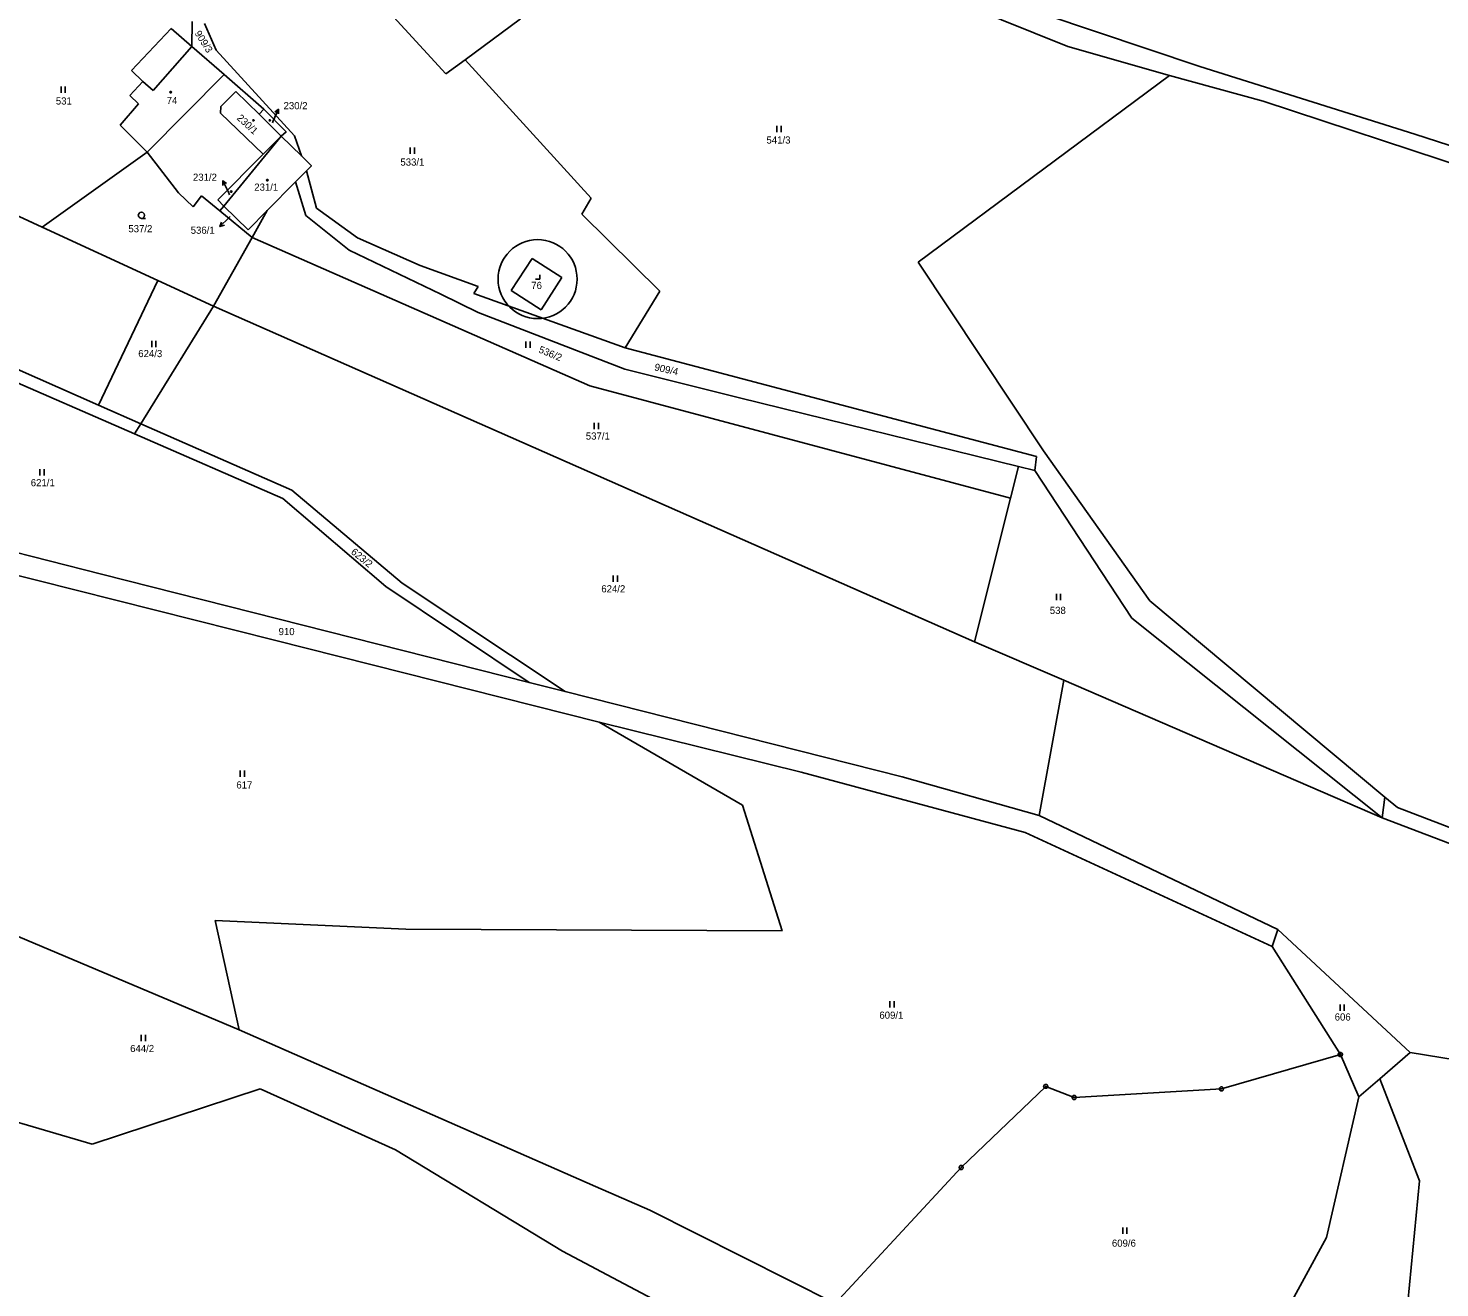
# Model space of a CAD drawing. Extents: x -580551 to -575069, y -1073031 to -1067931.
# Drawn here: x -578084.3 to -577749.4, y -1070721.5 to -1070422.6 of the extents above; entities that cross this region are included whole.
import ezdxf

# ---------------------------------------------------------------- set-up
doc = ezdxf.new("R2010")
doc.units = 0
for name, color, linetype in [('Druh pozemku', 7, 'Continuous'), ('Geodetické body', 7, 'Continuous'), ('Parcela', 7, 'Continuous'), ('Parcelní číslo', 7, 'Continuous'), ('Parcelní číslo_stavba', 7, 'Continuous'), ('Pomocná vrstva', 7, 'Continuous'), ('SR - hranice státu', 7, 'Continuous'), ('stavební parcely', 7, 'Continuous'), ('Vnitřní kresba', 7, 'Continuous'), ('Vrstva 6', 7, 'Continuous')]:
    doc.layers.add(name, color=color, linetype=linetype)

msp = doc.modelspace()

# ---------------------------------------------------------------- linework, layer by layer
at = {"layer": 'Druh pozemku'}
for p, q in [((-578076.49, -1070436.43), (-578076.49, -1070437.93)), ((-578075.49, -1070437.93), (-578075.49, -1070436.43)), ((-577906.63, -1070445.75), (-577906.63, -1070447.25)), ((-577905.63, -1070447.25), (-577905.63, -1070445.75)), ((-577993.62, -1070450.85), (-577993.62, -1070452.35)), ((-577992.62, -1070452.35), (-577992.62, -1070450.85)), ((-578054.97, -1070496.75), (-578054.97, -1070498.25)), ((-578053.97, -1070498.25), (-578053.97, -1070496.75)), ((-577966.19, -1070496.89), (-577966.19, -1070498.39)), ((-577965.19, -1070498.39), (-577965.19, -1070496.89)), ((-577949.96, -1070516.2), (-577949.96, -1070517.7)), ((-577948.96, -1070517.7), (-577948.96, -1070516.2)), ((-578081.49, -1070527.19), (-578081.49, -1070528.69)), ((-578080.49, -1070528.69), (-578080.49, -1070527.19)), ((-577945.49, -1070552.45), (-577945.49, -1070553.95)), ((-577944.49, -1070553.95), (-577944.49, -1070552.45)), ((-577840.32, -1070556.76), (-577840.32, -1070558.26)), ((-577839.32, -1070558.26), (-577839.32, -1070556.76)), ((-578033.98, -1070598.73), (-578033.98, -1070600.23)), ((-578032.98, -1070600.23), (-578032.98, -1070598.73)), ((-577879.8, -1070653.48), (-577879.8, -1070654.98)), ((-577878.8, -1070654.98), (-577878.8, -1070653.48)), ((-577773.02, -1070654.22), (-577773.02, -1070655.72)), ((-577772.02, -1070655.72), (-577772.02, -1070654.22)), ((-578057.48, -1070661.46), (-578057.48, -1070662.96)), ((-578056.48, -1070662.96), (-578056.48, -1070661.46)), ((-577824.57, -1070707.17), (-577824.57, -1070708.67)), ((-577823.57, -1070708.67), (-577823.57, -1070707.17))]:
    msp.add_line(p, q, dxfattribs=at)
for points in [[(-578050.38, -1070437.59), (-578050.29, -1070437.74), (-578050.38, -1070437.89), (-578050.56, -1070437.89), (-578050.65, -1070437.74), (-578050.56, -1070437.59)], [(-578030.75, -1070444.28), (-578030.66, -1070444.43), (-578030.75, -1070444.58), (-578030.93, -1070444.58), (-578031.02, -1070444.43), (-578030.93, -1070444.28)], [(-578026.85, -1070444.28), (-578026.76, -1070444.43), (-578026.85, -1070444.58), (-578027.03, -1070444.58), (-578027.12, -1070444.43), (-578027.03, -1070444.28)], [(-578027.45, -1070458.48), (-578027.36, -1070458.63), (-578027.45, -1070458.78), (-578027.63, -1070458.78), (-578027.72, -1070458.63), (-578027.63, -1070458.48)], [(-578036.02, -1070461.19), (-578035.93, -1070461.34), (-578036.02, -1070461.49), (-578036.2, -1070461.49), (-578036.29, -1070461.34), (-578036.2, -1070461.19)]]:
    msp.add_lwpolyline(points, close=True, dxfattribs=at)
for points in [[(-578057.41, -1070467.69), (-578057.79, -1070467.59), (-578058.06, -1070467.32), (-578058.16, -1070466.95), (-578058.06, -1070466.58), (-578057.79, -1070466.31), (-578057.42, -1070466.21), (-578057.05, -1070466.31), (-578056.78, -1070466.58), (-578056.68, -1070466.96), (-578056.78, -1070467.34), (-578057.05, -1070467.61), (-578057.43, -1070467.71), (-578056.43, -1070467.71)], [(-577963.91, -1070482.11), (-577962.91, -1070482.11), (-577962.91, -1070481.11)]]:
    msp.add_lwpolyline(points, dxfattribs=at)
at = {"layer": 'Geodetické body'}
for p, q in [((-577773.06, -1070666.13), (-577772.82, -1070666.13)), ((-577842.96, -1070673.67), (-577842.72, -1070673.67)), ((-577836.22, -1070676.32), (-577835.98, -1070676.32)), ((-577801.28, -1070674.28), (-577801.04, -1070674.28)), ((-577863.02, -1070692.92), (-577862.78, -1070692.92))]:
    msp.add_line(p, q, dxfattribs=at)
for points in [[(-577772.79, -1070665.65), (-577772.54, -1070665.83), (-577772.44, -1070666.12), (-577772.54, -1070666.41), (-577772.79, -1070666.59), (-577773.1, -1070666.59), (-577773.35, -1070666.41), (-577773.45, -1070666.12), (-577773.35, -1070665.83), (-577773.1, -1070665.65)], [(-577842.69, -1070673.19), (-577842.44, -1070673.37), (-577842.34, -1070673.66), (-577842.44, -1070673.95), (-577842.69, -1070674.13), (-577843, -1070674.13), (-577843.25, -1070673.95), (-577843.35, -1070673.66), (-577843.25, -1070673.37), (-577843, -1070673.19)], [(-577801.01, -1070673.8), (-577800.76, -1070673.98), (-577800.66, -1070674.27), (-577800.76, -1070674.56), (-577801.01, -1070674.74), (-577801.32, -1070674.74), (-577801.57, -1070674.56), (-577801.67, -1070674.27), (-577801.57, -1070673.98), (-577801.32, -1070673.8)], [(-577835.95, -1070675.84), (-577835.7, -1070676.02), (-577835.6, -1070676.31), (-577835.7, -1070676.6), (-577835.95, -1070676.78), (-577836.26, -1070676.78), (-577836.51, -1070676.6), (-577836.61, -1070676.31), (-577836.51, -1070676.02), (-577836.26, -1070675.84)], [(-577862.75, -1070692.44), (-577862.5, -1070692.62), (-577862.4, -1070692.91), (-577862.5, -1070693.2), (-577862.75, -1070693.38), (-577863.06, -1070693.38), (-577863.31, -1070693.2), (-577863.41, -1070692.91), (-577863.31, -1070692.62), (-577863.06, -1070692.44)]]:
    msp.add_lwpolyline(points, close=True, dxfattribs=at)
at = {"layer": 'Parcela'}
for p, q in [((-577858.45, -1070414.11), (-577806.32, -1070431.64)), ((-577985.2, -1070433.39), (-578000.19, -1070417.03)), ((-577861.42, -1070417.31), (-577837.64, -1070426.87)), ((-578050.36, -1070422.66), (-578059.76, -1070432.64)), ((-578045.43, -1070426.94), (-578050.36, -1070422.66)), ((-578045.35, -1070420.96), (-578045.43, -1070426.94)), ((-578039.68, -1070427.74), (-578042.48, -1070421.46)), ((-577980.64, -1070430.04), (-577967.46, -1070420.37)), ((-578037.79, -1070433.58), (-578045.43, -1070426.94)), ((-578021.11, -1070448.13), (-578039.68, -1070427.74)), ((-577837.64, -1070426.87), (-577813.45, -1070433.76)), ((-578059.76, -1070432.64), (-578057.07, -1070435.25)), ((-577985.2, -1070433.39), (-577980.64, -1070430.04)), ((-577950.73, -1070462.87), (-577980.64, -1070430.04)), ((-577806.32, -1070431.64), (-577755.23, -1070447.68)), ((-578057.07, -1070435.25), (-578060.17, -1070438.55)), ((-578028.34, -1070441.78), (-578037.79, -1070433.58)), ((-577873.09, -1070478.05), (-577813.45, -1070433.76)), ((-577813.45, -1070433.76), (-577791.25, -1070439.87)), ((-578058.08, -1070440.52), (-578060.17, -1070438.55)), ((-578035, -1070437.61), (-578038.57, -1070441.16)), ((-578029.52, -1070442.98), (-578035, -1070437.61)), ((-578062.5, -1070445.61), (-578058.08, -1070440.52)), ((-578038.57, -1070441.16), (-578038.69, -1070442.76)), ((-578038.69, -1070442.76), (-578028.5, -1070452.45)), ((-578028.34, -1070441.78), (-578029.52, -1070442.98)), ((-578029.52, -1070442.98), (-578024.23, -1070448.15)), ((-578023.11, -1070447.18), (-578028.34, -1070441.78)), ((-577791.25, -1070439.87), (-577736.35, -1070458)), ((-578056.05, -1070452.02), (-578062.5, -1070445.61)), ((-578037.85, -1070464.77), (-578024.23, -1070448.15)), ((-578028.5, -1070452.45), (-578024.23, -1070448.15)), ((-578024.23, -1070448.15), (-578023.11, -1070447.18)), ((-578019.47, -1070452.88), (-578024.23, -1070448.15)), ((-578019.47, -1070452.88), (-578021.11, -1070448.13)), ((-577755.23, -1070447.68), (-577706.55, -1070463.5)), ((-578081, -1070469.8), (-578056.05, -1070452.02)), ((-578048.63, -1070461.67), (-578056.05, -1070452.02)), ((-578028.5, -1070452.45), (-578039.3, -1070463.33)), ((-578017.1, -1070455.23), (-578019.47, -1070452.88)), ((-578020.86, -1070459.03), (-578018.26, -1070456.4)), ((-578018.26, -1070456.4), (-578017.1, -1070455.23)), ((-578015.87, -1070465.23), (-578018.26, -1070456.4)), ((-578081, -1070469.8), (-578108.53, -1070457.02)), ((-578027.58, -1070465.83), (-578020.86, -1070459.03)), ((-578018.38, -1070467.02), (-578020.86, -1070459.03)), ((-578045.14, -1070464.94), (-578048.63, -1070461.67)), ((-578043.16, -1070462.33), (-578045.14, -1070464.94)), ((-578038.81, -1070465.92), (-578043.16, -1070462.33)), ((-577952.89, -1070466.69), (-577950.73, -1070462.87)), ((-578039.3, -1070463.33), (-578037.85, -1070464.77)), ((-578037.85, -1070464.77), (-578038.81, -1070465.92)), ((-578031.16, -1070472.23), (-578038.81, -1070465.92)), ((-578037.85, -1070464.77), (-578032.12, -1070470.43)), ((-578032.12, -1070470.43), (-578027.58, -1070465.83)), ((-578031.16, -1070472.23), (-578027.58, -1070465.83)), ((-578006.17, -1070472.31), (-578015.87, -1070465.23)), ((-578053.52, -1070482.42), (-578081, -1070469.8)), ((-578008.12, -1070475.24), (-578018.38, -1070467.02)), ((-577934.42, -1070484.95), (-577952.89, -1070466.69)), ((-578040.28, -1070488.5), (-578031.16, -1070472.23)), ((-578031.16, -1070472.23), (-577951.01, -1070507.41)), ((-577991.26, -1070478.87), (-578006.17, -1070472.31)), ((-577986.41, -1070485.64), (-578008.12, -1070475.24)), ((-577977.51, -1070483.83), (-577991.26, -1070478.87)), ((-577964.73, -1070477.2), (-577969.65, -1070484.81)), ((-577964.73, -1070477.2), (-577957.68, -1070481.75)), ((-577843.37, -1070522.88), (-577873.09, -1070478.05)), ((-578040.28, -1070488.5), (-578053.52, -1070482.42)), ((-577957.68, -1070481.75), (-577962.6, -1070489.37)), ((-577977.48, -1070490.01), (-577986.41, -1070485.64)), ((-577978.51, -1070485.51), (-577977.51, -1070483.83)), ((-577942.6, -1070498.45), (-577978.51, -1070485.51)), ((-577962.6, -1070489.37), (-577969.65, -1070484.81)), ((-577942.6, -1070498.45), (-577934.42, -1070484.95)), ((-578040.28, -1070488.5), (-578057.58, -1070516.47)), ((-577859.74, -1070568.14), (-578040.28, -1070488.5)), ((-578059.03, -1070518.81), (-578118.06, -1070493.1)), ((-578067.62, -1070512.04), (-578117.01, -1070490.23)), ((-577942.71, -1070503.45), (-577977.48, -1070490.01)), ((-577845.02, -1070524.18), (-577942.6, -1070498.45)), ((-577915.51, -1070510.28), (-577942.71, -1070503.45)), ((-577951.01, -1070507.41), (-577851.18, -1070534.1)), ((-578057.58, -1070516.47), (-578067.62, -1070512.04)), ((-577849.28, -1070526.57), (-577915.51, -1070510.28)), ((-578057.58, -1070516.47), (-578059.03, -1070518.81)), ((-578021.77, -1070532.22), (-578057.58, -1070516.47)), ((-578023.85, -1070534.14), (-578059.03, -1070518.81)), ((-577818.13, -1070558.45), (-577843.37, -1070522.88)), ((-578066.89, -1070552.12), (-578168.38, -1070526.44)), ((-577851.18, -1070534.1), (-577849.28, -1070526.57)), ((-577845.44, -1070527.51), (-577849.28, -1070526.57)), ((-577845.44, -1070527.51), (-577845.02, -1070524.18)), ((-577822.38, -1070562.53), (-577845.44, -1070527.51)), ((-577995.56, -1070554.22), (-578021.77, -1070532.22)), ((-577999.43, -1070555.03), (-578023.85, -1070534.14)), ((-577859.74, -1070568.14), (-577851.18, -1070534.1)), ((-578128.28, -1070541.99), (-578025.83, -1070567.81)), ((-577965.4, -1070577.8), (-578066.89, -1070552.12)), ((-577965.4, -1070577.8), (-577999.43, -1070555.03)), ((-577956.88, -1070579.95), (-577995.56, -1070554.22)), ((-577762.39, -1070605.01), (-577818.13, -1070558.45)), ((-577763.03, -1070609.98), (-577822.38, -1070562.53)), ((-578025.83, -1070567.81), (-577948.83, -1070587.22)), ((-577838.56, -1070577.3), (-577859.74, -1070568.14)), ((-577956.88, -1070579.95), (-577965.4, -1070577.8)), ((-577876.88, -1070600.19), (-577956.88, -1070579.95)), ((-577844.43, -1070609.36), (-577838.56, -1070577.3)), ((-577763.03, -1070609.98), (-577838.56, -1070577.3)), ((-577948.83, -1070587.22), (-577900.88, -1070599.08)), ((-577900.88, -1070599.08), (-577847.72, -1070613.45)), ((-577844.43, -1070609.36), (-577876.88, -1070600.19)), ((-577763.03, -1070609.98), (-577762.39, -1070605.01)), ((-577759.37, -1070607.53), (-577762.39, -1070605.01)), ((-577787.8, -1070636.45), (-577844.43, -1070609.36)), ((-577644.65, -1070654.99), (-577763.03, -1070609.98)), ((-577640.62, -1070652.74), (-577759.37, -1070607.53)), ((-577847.72, -1070613.45), (-577789.13, -1070640.45)), ((-578034.23, -1070660.29), (-578144.08, -1070613.9)), ((-577787.8, -1070636.45), (-577789.13, -1070640.45)), ((-577756.39, -1070665.66), (-577787.8, -1070636.45)), ((-577772.94, -1070666.13), (-577789.13, -1070640.45)), ((-577949.7, -1070697.42), (-578034.23, -1070660.29)), ((-577801.16, -1070674.28), (-577772.94, -1070666.13)), ((-577772.94, -1070666.13), (-577768.53, -1070676.17)), ((-577756.39, -1070665.66), (-577763.54, -1070671.85)), ((-577737.46, -1070668.67), (-577756.39, -1070665.66)), ((-577862.9, -1070692.92), (-577842.84, -1070673.67)), ((-577842.84, -1070673.67), (-577836.1, -1070676.32)), ((-577763.54, -1070671.85), (-577768.53, -1070676.17)), ((-577763.54, -1070671.85), (-577754.19, -1070696.06)), ((-578069.14, -1070687.4), (-578103.62, -1070677.27)), ((-578029.21, -1070674.26), (-578069.14, -1070687.4)), ((-577997.17, -1070688.7), (-578029.21, -1070674.26)), ((-577836.1, -1070676.32), (-577801.16, -1070674.28)), ((-577768.53, -1070676.17), (-577776.19, -1070709.56)), ((-577957.53, -1070712.79), (-577997.17, -1070688.7)), ((-577892.84, -1070725.17), (-577862.9, -1070692.92)), ((-577936.81, -1070703.08), (-577949.7, -1070697.42)), ((-577754.19, -1070696.06), (-577761.83, -1070777.01)), ((-577892.84, -1070725.17), (-577936.81, -1070703.08)), ((-577776.19, -1070709.56), (-577804.68, -1070761.47)), ((-577916.6, -1070734.36), (-577957.53, -1070712.79))]:
    msp.add_line(p, q, dxfattribs=at)
at = {"layer": 'Pomocná vrstva'}
for p, q in [((-578024.931, -1070441.8), (-578026.13, -1070444.55)), ((-578026.32, -1070444.99), (-578026.13, -1070444.55)), ((-578038.095, -1070458.769), (-578036.79, -1070461.47)), ((-578036.5, -1070462.08), (-578036.79, -1070461.47)), ((-578038.809, -1070469.654), (-578036.67, -1070467.55)), ((-578036.36, -1070467.24), (-578036.67, -1070467.55))]:
    msp.add_line(p, q, dxfattribs=at)
for points in [[(-578025.789, -1070442.517), (-578024.931, -1070441.8), (-578024.872, -1070442.917)], [(-578038.11, -1070459.887), (-578038.095, -1070458.769), (-578037.21, -1070459.452)], [(-578037.745, -1070469.309), (-578038.809, -1070469.654), (-578038.446, -1070468.596)]]:
    msp.add_lwpolyline(points, dxfattribs=at)
at = {"layer": 'SR - hranice státu'}
for points in [[(-578028.34, -1070441.78), (-578037.79, -1070433.58), (-578045.43, -1070426.94), (-578045.35, -1070420.96)], [(-578040.28, -1070488.5), (-578031.16, -1070472.23), (-578027.58, -1070465.83), (-578020.86, -1070459.03), (-578017.1, -1070455.23), (-578019.47, -1070452.88), (-578024.23, -1070448.15), (-578023.11, -1070447.18), (-578028.34, -1070441.78)], [(-578109.99, -1070456.34), (-578108.53, -1070457.02), (-578081, -1070469.8), (-578053.52, -1070482.42), (-578040.28, -1070488.5)]]:
    msp.add_lwpolyline(points, dxfattribs=at)
at = {"layer": 'stavební parcely'}
msp.add_circle((-577963.41, -1070482.11), 9.375, dxfattribs=at)
at = {"layer": 'Vnitřní kresba'}
for p, q in [((-578054.67, -1070437.33), (-578045.43, -1070426.94)), ((-578057.07, -1070435.25), (-578054.67, -1070437.33)), ((-578056.05, -1070452.02), (-578037.79, -1070433.58))]:
    msp.add_line(p, q, dxfattribs=at)
at = {"layer": 'Vrstva 6'}
for p, q in [((-578067.62, -1070512.04), (-578053.52, -1070482.42)), ((-577914.77, -1070606.9), (-577948.83, -1070587.22)), ((-577905.41, -1070636.76), (-577914.77, -1070606.9)), ((-578034.23, -1070660.29), (-578039.94, -1070634.32)), ((-578039.94, -1070634.32), (-577994.66, -1070636.34)), ((-577994.66, -1070636.34), (-577905.41, -1070636.76))]:
    msp.add_line(p, q, dxfattribs=at)

# ---------------------------------------------------------------- texts
at = {"layer": 'Parcelní číslo'}
for s, rotation, p in [('909/3', 302.57901, (-578044.875, -1070423.793)), ('536/2', 337.52944, (-577963.329, -1070499.452)), ('909/4', 347.61349, (-577935.812, -1070503.745)), ('623/2', 321.08555, (-578007.848, -1070547.117))]:
    msp.add_text(s, height=1.7, rotation=rotation, dxfattribs=at).set_placement(p)
for s, height, p in [('531', 1.7, (-578077.725, -1070440.68)), ('541/3', 1.7, (-577909.11, -1070449.94)), ('533/1', 1.7, (-577995.967, -1070455.18)), ('537/2', 1.7, (-578060.517, -1070470.99)), ('536/1', 0.1, (-578036.549, -1070467.24)), ('624/3', 1.7, (-578058.171, -1070500.62)), ('537/1', 1.7, (-577951.975, -1070520.19)), ('621/1', 1.7, (-578083.67, -1070531.26)), ('624/2', 1.7, (-577948.299, -1070556.45)), ('538', 1.7, (-577841.88, -1070561.56)), ('910', 1.7, (-578024.871, -1070566.59)), ('617', 1.7, (-578034.902, -1070602.99)), ('609/1', 1.7, (-577882.316, -1070657.62)), ('606', 1.7, (-577774.288, -1070658.05)), ('644/2', 1.7, (-578060.094, -1070665.53)), ('609/6', 1.7, (-577827.143, -1070711.72))]:
    msp.add_text(s, height=height, dxfattribs=at).set_placement(p)
at = {"layer": 'Parcelní číslo_stavba'}
for s, height, p in [('74', 1.7, (-578051.421, -1070440.57)), ('230/2', 0.1, (-578026.537, -1070444.99)), ('231/1', 1.7, (-578030.647, -1070461.13)), ('231/2', 0.1, (-578036.695, -1070462.08)), ('76', 1.7, (-577964.911, -1070484.45))]:
    msp.add_text(s, height=height, dxfattribs=at).set_placement(p)
msp.add_text('230/1', height=1.7, rotation=317.18944, dxfattribs=at).set_placement((-578034.918, -1070444.058))
at = {"layer": 'Pomocná vrstva'}
for s, p in [('230/2', (-578023.693, -1070441.8)), ('231/2', (-578045.196, -1070458.77)), ('536/1', (-578045.729, -1070471.35))]:
    msp.add_text(s, height=1.7, dxfattribs=at).set_placement(p)

doc.saveas('drawing.dxf')
